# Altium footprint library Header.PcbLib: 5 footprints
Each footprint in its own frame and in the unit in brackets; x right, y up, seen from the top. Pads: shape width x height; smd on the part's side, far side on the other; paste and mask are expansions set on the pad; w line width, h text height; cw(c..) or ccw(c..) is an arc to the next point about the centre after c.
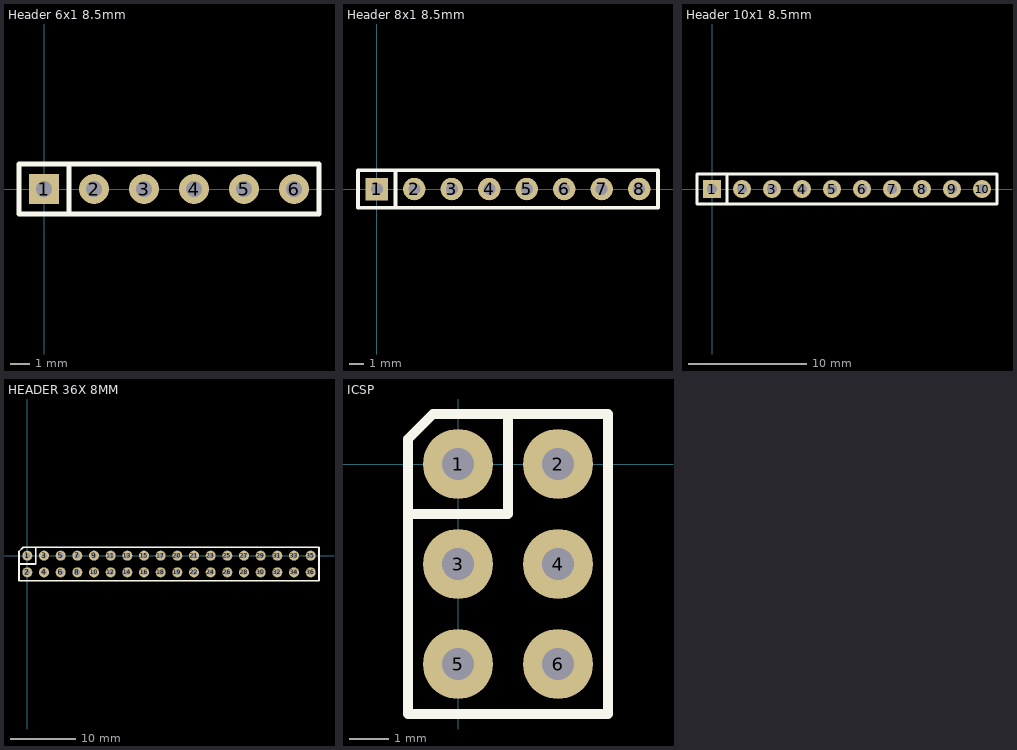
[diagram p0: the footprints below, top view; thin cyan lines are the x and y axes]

## Header 6x1 8.5mm [mil] "Stackable 6 pin header"
pads (6):
  rect 60x60 hole 32: 1(0,0)
  round 60 hole 32: 2(100,0) 3(200,0) 4(300,0) 5(400,0) 6(500,0)
Top Overlay:
  lines w10: 50,-50 -50,-50 -50,0 -50,50 50,50 ; 50,-50 50,50 ; 50,-50 550,-50 550,50 50,50
3D body "SIL_Socket06.stp": height 334.65, standoff -584.65, extent -49.99,-49.99 550.01,50.01

## Header 8x1 8.5mm [mil] "Stackable 8 pin header"
pads (8):
  rect 60x60 hole 32: 1(0,0)
  round 60 hole 32: 2(100,0) 3(200,0) 4(300,0) 5(400,0) 6(500,0) 7(600,0) 8(700,0)
Top Overlay:
  lines w10: 50,-50 50,50 ; -50,-50 -50,50 750,50 750,-50 -50,-50
3D body "SIL_Socket08_.stp": height 334.65, standoff -584.65, extent -50,-49.99 750,50.01

## Header 10x1 8.5mm [mil] "Stackable 10 pin header"
pads (10):
  rect 60x60 hole 32: 1(0,0)
  round 60 hole 32: 2(100,0) 3(200,0) 4(300,0) 5(400,0) 6(500,0) 7(600,0) 8(700,0) 9(800,0) 10(900,0)
Top Overlay:
  lines w10: 50,-50 -50,-50 -50,50 50,50 ; 50,-50 950,-50 950,50 50,50 ; 50,-50 50,50
3D body "SIL_Socket10.stp": height 334.65, standoff -584.65, extent -50,-50 950,50

## HEADER 36X 8MM [mil] "Stackable 10 pin header"
pads (36):
  round 60 hole 32: 1(0,0) 2(0,-100) 3(100,0) 4(100,-100) 5(200,0) 6(200,-100) 7(300,0) 8(300,-100) 9(400,0) 10(400,-100) 11(500,0) 12(500,-100) 13(600,0) 14(600,-100) 15(700,0) 16(700,-100) 17(800,0) 18(800,-100) 19(900,-100) 20(900,0) 21(1000,0) 22(1000,-100) 23(1100,0) 24(1100,-100) 25(1200,0) 26(1200,-100) 27(1300,0) 28(1300,-100) 29(1400,0) 30(1400,-100) 31(1500,0) 32(1500,-100) 33(1600,0) 34(1600,-100) 35(1700,0) 36(1700,-100)
Top Overlay:
  lines w10: -50,-50 50,-50 50,50 ; -50,-150 -50,25 -25,50 1750,50 1750,-150 -50,-150
3D body "SIL_Socket36.stp": height 334.65, standoff -584.65, extent -50,-150 1750,50

## ICSP [mil]
pads (6):
  round 70 hole 32: 1(0,0) 2(100,0) 3(0,-100) 4(100,-100) 5(0,-200) 6(100,-200)
Top Overlay:
  lines w10: -50,-50 50,-50 50,50 ; -50,-250 -50,25 -25,50 150,50 150,-250 -50,-250
3D body "ICSP.stp": height 484.65, standoff -105.84, extent -49.99,-249.99 150.01,50.01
